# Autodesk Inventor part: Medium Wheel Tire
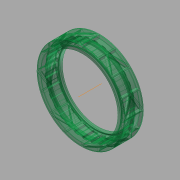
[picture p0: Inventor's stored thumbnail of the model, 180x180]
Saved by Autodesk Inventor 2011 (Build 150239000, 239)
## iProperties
Created: 2010-06
Part Number: Medium Wheel Tire
Document SubType Name: Modeling
Designer: kurdi
Density: 1 g/cm^3
Author: kurdi
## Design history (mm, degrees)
sketch "Sketch2"
  geometry: L1 (41.19, -9.063)-(45.906, -11.07); L2 (46.304, -11.151)-(50.495, -11.151); L3 (50.8, -10.846)-(50.8, -10.084); L4 (50.615, -9.803)-(48.289, -8.814); L5 (48.289, -8.814)-(48.289, 0); L6 (0, 0)-(48.289, 0); L7 (41.097, -8.923)-(41.097, -4.859); L8 (41.463, -4.56)-(42.454, -4.763); L9 (42.697, -5.062)-(42.697, -6.662); L10 (42.906, -6.951)-(43.896, -7.281); L11 (45.14, -6.606)-(46.105, -6.419); L12 (46.434, -6.02)-(46.434, 0); L13 (41.19, 9.063)-(45.906, 11.07); L14 (41.097, 8.923)-(41.097, 4.859); L15 (42.906, 6.951)-(43.896, 7.281); L16 (42.697, 5.062)-(42.697, 6.662); L17 (41.463, 4.56)-(42.454, 4.763); L18 (46.304, 11.151)-(50.495, 11.151); L19 (50.8, 10.846)-(50.8, 10.084); L20 (50.615, 9.803)-(48.289, 8.814); L21 (48.289, 8.814)-(48.289, 0); L22 (46.434, 6.02)-(46.434, 0); L23 (45.14, 6.606)-(46.105, 6.419); L24 (0, -15.699)-(0, 15.699) reference; A1 r 0.152 centre (41.25, -8.923) between (41.097, -8.923) and (41.19, -9.063); A2 r 1.016 centre (46.304, -10.135) between (45.906, -11.07) and (46.304, -11.151); A3 r 0.305 centre (41.402, -4.859) between (41.463, -4.56) and (41.097, -4.859); A4 r 0.305 centre (42.393, -5.062) between (42.697, -5.062) and (42.454, -4.763); A5 r 0.305 centre (43.002, -6.662) between (42.697, -6.662) and (42.906, -6.951); A6 r 0.406 centre (45.217, -7.005) between (45.14, -6.606) and (44.842, -6.849); A7 r 0.762 centre (44.137, -6.559) between (43.896, -7.281) and (44.842, -6.849); A8 r 0.406 centre (46.028, -6.02) between (46.105, -6.419) and (46.434, -6.02); A9 r 0.305 centre (50.495, -10.846) between (50.495, -11.151) and (50.8, -10.846); A10 r 0.305 centre (50.495, -10.084) between (50.8, -10.084) and (50.615, -9.803); A11 r 0.762 centre (44.137, 6.559) between (44.842, 6.849) and (43.896, 7.281); A12 r 0.305 centre (43.002, 6.662) between (42.906, 6.951) and (42.697, 6.662); A13 r 0.152 centre (41.25, 8.923) between (41.19, 9.063) and (41.097, 8.923); A14 r 0.305 centre (42.393, 5.062) between (42.454, 4.763) and (42.697, 5.062); A15 r 0.305 centre (41.402, 4.859) between (41.097, 4.859) and (41.463, 4.56); A16 r 1.016 centre (46.304, 10.135) between (46.304, 11.151) and (45.906, 11.07); A17 r 0.305 centre (50.495, 10.084) between (50.615, 9.803) and (50.8, 10.084); A18 r 0.305 centre (50.495, 10.846) between (50.8, 10.846) and (50.495, 11.151); A19 r 0.406 centre (45.217, 7.005) between (44.842, 6.849) and (45.14, 6.606); A20 r 0.406 centre (46.028, 6.02) between (46.434, 6.02) and (46.105, 6.419)
  constraints: 47 end point, 40 point on circle, 30 symmetric about line, 20 centre point, 19 tangent, 3 perpendicular, 2 parallel, 1 equal radius, 1 horizontal, 1 point on line, 1 vertical, 10 other
  dimensions: "d2" = 11.1506 distance between parallel lines of L6 L2; "d3" = 8.8138 distance of L4.end L5.end; "d4" = 0.1524 radius of A1; "d5" = 1.016 radius of A2; "d7" = 2.0066 vertical distance of L1.start L1.end; "d8" = 0.3048 radius of A3; "d9" = 4.064 distance of L7.start L7.end; "d11" = 0.9906 horizontal distance of L8.start L8.end; "d12" = 0.2032 vertical distance of L8.start L8.end; "d13" = 0.3048 radius of A4; "d14" = 0.3048 radius of A5; "d15" = 1.6002 distance of L9.start L9.end; "d16" = 0.4064 radius of A8; "d17" = 0.4064 radius of A6; "d18" = 0.762 radius of A7; "d19" = 0.9906 horizontal distance of L10.start L10.end; "d20" = 0.3302 vertical distance of L10.start L10.end; "d21" = 0.3048 radius of A9; "d22" = 4.191 distance of L2.start L2.end; "d24" = 1.8542 distance between parallel lines of L5 L12; "d25" = 0.9652 horizontal distance of L11.start L11.end; "d26" = 41.0972 distance from line of L7 L6.start; "d28" = 6.0198 distance of L12.start L12.end; "d29" = 5.207 distance from line of A2.centre L7; "d30" = 1.0668 distance from line of A10.centre L2
revolve "Revolution1" sketch "Sketch2" stored, may be unused: angle "d31" = 90 deg
sketch "Sketch3"
  geometry: L1 (0, 0)-(0, 46.482); L2 (1.867, 46.444)-(0, 0); L3 (1.867, 46.444)-(2.38, 44.386); L4 (-1.867, 46.444)-(0, 0); L5 (-1.867, 46.444)-(-2.38, 44.386); L6 (-11.482, 45.041)-(-11.556, 42.921); L7 (-7.83, 45.818)-(-6.9, 43.911); L8 (-20.596, 41.67)-(-20.228, 39.581); L9 (-17.185, 43.188)-(-15.879, 41.517); L10 (-28.81, 36.477)-(-28.015, 34.51); L11 (-25.789, 38.672)-(-24.164, 37.308); L12 (-35.764, 29.69)-(-34.578, 27.931); L13 (-33.266, 32.465)-(-31.393, 31.469); L14 (-41.156, 21.605)-(-39.63, 20.132); L15 (-39.289, 24.839)-(-37.25, 24.254); L16 (-44.748, 12.577)-(-42.949, 11.453); L17 (-43.594, 16.128)-(-41.478, 15.98); L18 (-46.385, 2.998)-(-44.392, 2.273); L19 (-45.995, 6.711)-(-43.894, 7.007); L20 (-45.995, -6.711)-(-43.894, -7.007); L21 (-46.385, -2.998)-(-44.392, -2.273); L22 (-43.594, -16.128)-(-41.478, -15.98); L23 (-44.748, -12.577)-(-42.949, -11.453); L24 (-39.289, -24.839)-(-37.25, -24.254); L25 (-41.156, -21.605)-(-39.63, -20.132); L26 (-33.266, -32.465)-(-31.393, -31.469); L27 (-35.764, -29.69)-(-34.578, -27.931); L28 (-25.789, -38.672)-(-24.164, -37.308); L29 (-28.81, -36.477)-(-28.015, -34.51); L30 (-17.185, -43.188)-(-15.879, -41.517); L31 (-20.596, -41.67)-(-20.228, -39.581); L32 (-7.83, -45.818)-(-6.9, -43.911); L33 (-11.482, -45.041)-(-11.556, -42.921); L34 (1.867, -46.444)-(2.38, -44.386); L35 (-1.867, -46.444)-(-2.38, -44.386); L36 (11.482, -45.041)-(11.556, -42.921); L37 (7.83, -45.818)-(6.9, -43.911); L38 (20.596, -41.67)-(20.228, -39.581); L39 (17.185, -43.188)-(15.879, -41.517); L40 (28.81, -36.477)-(28.015, -34.51); L41 (25.789, -38.672)-(24.164, -37.308); L42 (35.764, -29.69)-(34.578, -27.931); L43 (33.266, -32.465)-(31.393, -31.469); L44 (41.156, -21.605)-(39.63, -20.132); L45 (39.289, -24.839)-(37.25, -24.254); L46 (44.748, -12.577)-(42.949, -11.453); L47 (43.594, -16.128)-(41.478, -15.98); L48 (46.385, -2.998)-(44.392, -2.273); L49 (45.995, -6.711)-(43.894, -7.007); L50 (45.995, 6.711)-(43.894, 7.007); L51 (46.385, 2.998)-(44.392, 2.273); L52 (43.594, 16.128)-(41.478, 15.98); L53 (44.748, 12.577)-(42.949, 11.453); L54 (39.289, 24.839)-(37.25, 24.254); L55 (41.156, 21.605)-(39.63, 20.132); L56 (33.266, 32.465)-(31.393, 31.469); L57 (35.764, 29.69)-(34.578, 27.931); L58 (25.789, 38.672)-(24.164, 37.308); L59 (28.81, 36.477)-(28.015, 34.51); L60 (17.185, 43.188)-(15.879, 41.517); L61 (20.596, 41.67)-(20.228, 39.581); L62 (7.83, 45.818)-(6.9, 43.911); L63 (11.482, 45.041)-(11.556, 42.921); A1 r 44.45 centre (0, 0) between (6.9, 43.911) and (2.38, 44.386); A2 r 44.45 centre (0, 0) between (1.785, 44.414) and (11.556, 42.921); A3 r 46.482 centre (0, 0) between (7.83, 45.818) and (1.867, 46.444); A4 r 46.482 centre (0, 0) between (0, 46.482) and (11.482, 45.041); 1 further point
  constraints: 126 end point, 8 point on circle, 4 centre point, 2 coincident, 2 symmetric about line, 1 point on line, 1 vertical, 181 other
  dimensions: "d35" = 14 deg angle of L1 L3; "d38" = 360 deg dimension on point (0, 0) L4.start (derived); "d40" = 3.7338 distance of L2.start L4.start; "d41" = 46.482 radius of A4; "d42" = 44.45 radius of A2
extrude "Extrusion1" join sketch "Sketch3" stored distance "d43" = 17.78; taper "d44" = 0 deg
workplane "Work Plane1"
workaxis "Work Axis1"
sketch "Sketch6"
  geometry: L1 (0, 0)-(0, 50.8); L2 (0.635, 50.796)-(1.82, 48.254); L3 (-0.635, 50.796)-(-1.82, 48.254); A1 r 48.289 centre (0, 0) between (1.82, 48.254) and (-1.82, 48.254) reference; A2 r 50.8 centre (0, 0) between (0.635, 50.796) and (-0.635, 50.796); A3 r 48.289 centre (0, 0) between (1.82, 48.254) and (-1.82, 48.254); 2 further points
  constraints: 7 point on circle, 6 end point, 2 centre point, 1 concentric, 1 vertical, 1 vertical alignment, 2 other
  dimensions: "d67" = 1.27 distance of L2.start L3.start; "d68" = 25 deg angle of L1 L3; "d69" = 25 deg angle of L1 L2
extrude "Extrusion2" join sketch "Sketch6" stored distance "d70" = 20.828; taper "d71" = 0 deg
pattern_circular "Circular Pattern3" dims angle "d73" = 360 deg
workplane "Work Plane3"
workplane "Work Plane5"
sketch "Sketch7"
  geometry: L1 (-5.677, 16.916)-(14.491, 16.916) reference; L2 (14.491, 18.161)-(-5.677, 18.161) reference; L3 (14.491, -1.658)-(-5.677, -1.658) reference; L4 (-5.677, -2.904)-(14.491, -2.904) reference; L5 (4.407, -2.904)-(4.407, -1.658); L6 (-5.677, 18.161)-(-5.677, 16.916); L7 (14.491, 18.161)-(14.491, 16.916); L8 (-6.058, 16.535)-(14.872, 16.535); L9 (14.872, 16.535)-(14.872, 18.542); L10 (14.872, 18.542)-(-6.058, 18.542); L11 (-6.058, 18.542)-(-6.058, 16.535); L12 (-6.058, 17.539)-(4.407, -2.281); L13 (4.407, -2.281)-(14.872, 17.539); L14 (-6.058, 16.179)-(3.689, -2.281); L15 (5.125, -2.281)-(14.872, 16.179); L16 (3.689, -2.281)-(5.125, -2.281); L17 (4.407, -0.921)-(14.154, 17.539); L18 (-5.34, 17.539)-(4.407, -0.921); L19 (14.872, 17.539)-(14.872, 16.179); L20 (14.872, 17.539)-(14.154, 17.539); L21 (-6.058, 17.539)-(-5.34, 17.539); L22 (-6.058, 17.539)-(-6.058, 16.179)
  constraints: 36 end point, 7 parallel, 6 midpoint, 4 perpendicular, 1 collinear, 3 other
  dimensions: "d80" = 0.381 distance between parallel lines of L8 L1; "d81" = 0.635 distance between parallel lines of L14 L12; "d84" = 0.635 distance between parallel lines of L15 L13; "d85" = 0.635 distance between parallel lines of L18 L12; "d86" = 0.635 distance between parallel lines of L17 L13
extrude "Extrusion3" join sketch "Sketch7" stored distance "d88" = 20.828; taper "d89" = 0 deg
sketch "Sketch8"
  geometry: C1 r 50.8 at (0, 0) reference; C2 r 57.15 at (0, 0); 1 further point
  constraints: 1 centre point, 1 coincident
  dimensions: "d90" = 114.3 diameter of C2
extrude "Extrusion4" cut sketch "Sketch8" stored distance "d91" = 0; taper "d92" = 0 deg
workplane "Work Plane6"
sketch "Sketch9"
  geometry: L1 (0, 0)-(2.527, 0.216) reference; L2 (2.634, -1.049)-(0.224, -1.255) reference; L3 (0, 0)-(2.426, 1.395); L4 (2.426, 1.395)-(2.527, 0.216); L5 (0.224, -1.255)-(0, -1.275); L6 (0, -1.275)-(2.634, -2.239); L7 (2.634, -2.239)-(2.634, -1.049); 1 further point
  constraints: 10 end point, 2 perpendicular, 1 vertical, 1 vertical alignment
  dimensions: "d93" = 25 deg angle of L1 L3; "d94" = 25 deg angle of L6 L2
sketch "3D Sketch1"
sweep "Sweep1" sketch "Sketch9", "3D Sketch1" dims "d96" = 0
workplane "Work Plane7"
sketch "Sketch10"
  geometry: L1 (-2.554, 0.184)-(-0.188, 0.014) reference; L2 (-2.884, 0.208)-(0, 0) reference; L3 (0, 0)-(-2.884, -1.1); L4 (-2.884, -1.1)-(-2.884, 0.208); 1 further point
  constraints: 4 end point, 1 vertical
  dimensions: "d97" = 25 deg angle of L1 L3
sketch "3D Sketch2"
sweep "Sweep2" sketch "Sketch10", "3D Sketch2" dims "d98" = 0
mirror "Mirror1"
sketch "Sketch11"
  geometry: A1 r 50.8 centre (0, 0) between (18.852, 47.172) and (0.635, 50.796) reference; 1 further point
workplane "Work Plane8"
sketch "Sketch12"
  geometry: L1 (0, -10.084)-(-3.396, -10.084) reference; L2 (0, -20.168)-(0, 0) reference; L3 (0, -9.449)-(0, -10.719); L4 (0, -10.719)-(-4.112, -12.636); L5 (-4.112, -12.636)-(-4.112, -7.532); L6 (-4.112, -7.532)-(0, -9.449); L7 (-4.366, -4.064)-(-4.366, -16.104) reference; 2 further points
  constraints: 8 end point, 3 midpoint, 1 collinear, 1 parallel
  dimensions: "d99" = 25 deg angle of L6 L1; "d100" = 25 deg angle of L4 L1; "d101" = 1.27 distance of L3.end L3.start; "d102" = 0.254 distance between parallel lines of L7 L5
sweep "Sweep3" sketch "Sketch12" dims "d103" = 0
pattern_circular "Circular Pattern4" dims "d105" = 360 deg
fillet "Fillet1" dims "d107" = 0.3048
body "Solid1"
pattern_circular "Circular Pattern1" dims angle "d46" = 360 deg
other parameters: "d32" = 92.964, "d33" = 88.9, "d79" = 3.81, "d82" = 0.635, "d83" = 0.635
